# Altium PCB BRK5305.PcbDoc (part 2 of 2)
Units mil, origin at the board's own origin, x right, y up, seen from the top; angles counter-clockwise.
Board outline 4724.41 x 3149.61 mil, 4 copper layers (L1-Top, L2-Plane-1, L3-Plane-2, L4-Bottom), stack 60.6 mil thick; 66 components, 156 nets, 613 pads, 306 vias.
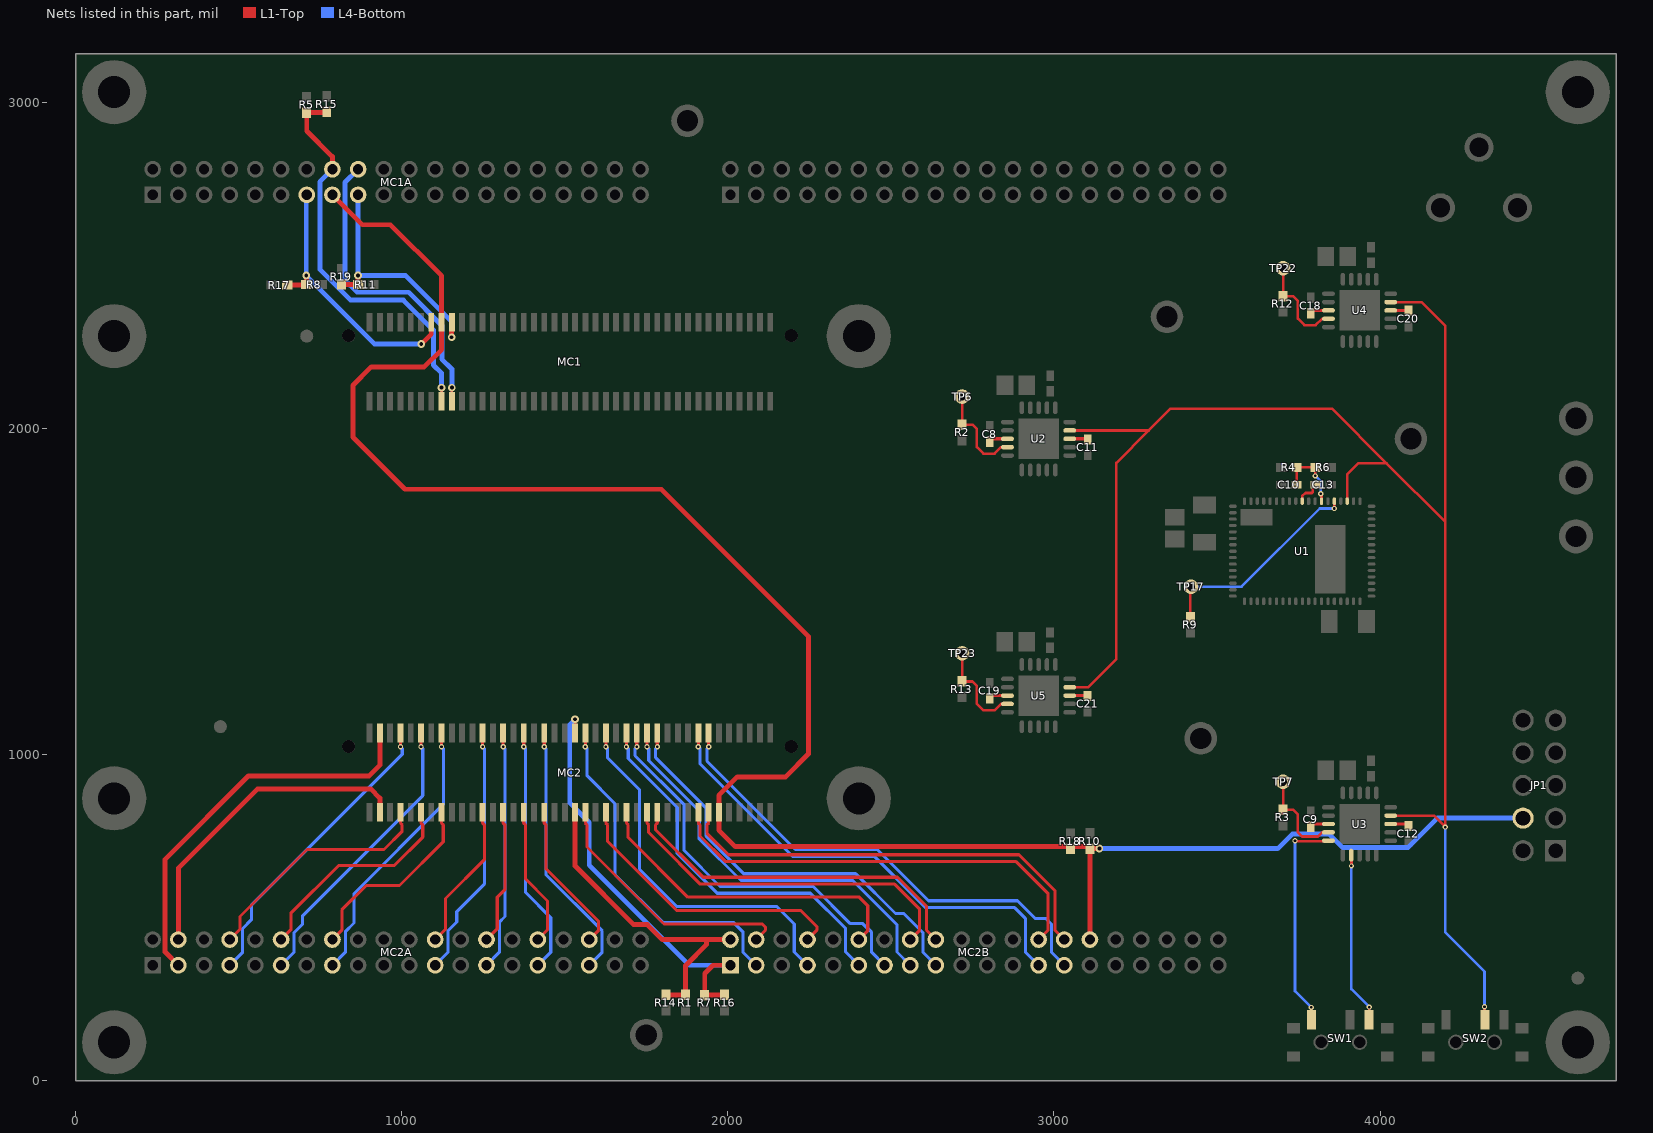
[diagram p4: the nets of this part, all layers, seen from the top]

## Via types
v1: diameter 16, hole 8, L1-Top to L4-Bottom, tented both sides, 140 vias
v2: diameter 23.62, hole 11.81, L1-Top to L4-Bottom, tented both sides, 74 vias
v3: diameter 15.99, hole 8, L1-Top to L4-Bottom, tented both sides, 52 vias
v4: diameter 30, hole 15, L1-Top to L4-Bottom, tented both sides, 40 vias

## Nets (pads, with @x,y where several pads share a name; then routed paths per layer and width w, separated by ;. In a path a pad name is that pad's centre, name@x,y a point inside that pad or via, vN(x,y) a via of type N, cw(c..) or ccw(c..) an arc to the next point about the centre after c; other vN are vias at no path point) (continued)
MC2-BN19: MC2.53 MC2B.13 | length 1221.2
  L1-Top w9.5: MC2.53@1720.47,1066.34 1720.47,1024.44 v1(1720.91,1024)
  L4-Bottom w9.5: v1(1720.91,1024) 1715.41,1018.5 1715.41,997 1865.71,846.7 1865.71,705.98 1975.7,596 2261.7,596 2375.7,482 2413.96,482 2440.96,455 2440.96,393.69 MC2B.13@2480.32,354.33
MC2-BN20: MC2.58 MC2B.18 | length 1097.6
  L1-Top w9.5: MC2.58@1783.46,823.43 1783.46,790.13 1778.22,784.88 1778.22,769.89 1924.11,624 2520,624 2608.93,535.07 2608.93,461.94 MC2B.18@2637.8,433.07
MC2-BN21: MC2.57 MC2B.17 | length 1286.4
  L1-Top w9.5: MC2.57@1783.46,1066.34 1783.47,1024.44 v1(1783.91,1024)
  L4-Bottom w9.5: v1(1783.91,1024) 1778.41,1018.5 1778.41,991 1933.35,836.05 1933.35,750.34 2048.7,635 2391.7,635 2513.85,512.85 2539.59,512.85 2598.44,454 2598.44,393.69 MC2B.17@2637.8,354.33
MC2-BN22: MC2.68 MC2B.28 | length 1368.2
  L1-Top w9.5: MC2.68@1940.95,823.43 1940.95,790.13 1935.7,784.88 1935.7,759.3 2002,693 2892.7,693 3003,582.7 3003,461.57 MC2B.28@3031.5,433.07
MC2-BN23: MC2.67 MC2B.27 | length 1494.7
  L1-Top w9.5: MC2.67@1940.95,1066.34 1940.95,1024.44 v1(1941.39,1024)
  L4-Bottom w9.5: v1(1941.39,1024) 1935.89,1018.5 1935.89,980.11 2055,861 2207,709 2458,709 2615,552 2887.84,552 2941.84,498 2975.14,498 2992.14,481 2992.14,393.69 MC2B.27@3031.5,354.33
MC2-BP0: MC2.8 MC2A.8 | length 749.8
  L1-Top w9.5: MC2A.8@472.44,433.07 504,464.63 504,503.7 709.3,709 945.31,709 1001.31,765 1001.31,784.88 996.06,790.13 MC2.8@996.06,823.43
MC2-BP1: MC2.7 MC2A.7 | length 933.5
  L1-Top w9.5: v1(996,1024) 996.06,1024.06 MC2.7@996.06,1066.34
  L4-Bottom w9.5: MC2A.7@472.44,354.33 512,393.89 512,467 538.76,493.76 538.76,538.32 1001.5,1001.06 1001.5,1018.5 v1(996,1024)
MC2-BP2: MC2.12 MC2A.12 | length 672.6
  L1-Top w9.5: MC2A.12@629.92,433.07 660,463.15 660,513.7 806.3,660 977.3,660 1064.3,747 1064.3,784.88 1059.06,790.13 MC2.12@1059.06,823.43
MC2-BP3: MC2.11 MC2A.11 | length 894.3
  L1-Top w9.5: v1(1058.99,1024) 1059.06,1024.06 MC2.11@1059.06,1066.34
  L4-Bottom w9.5: MC2A.11@629.92,354.33 669.48,393.89 669.48,454 696.24,480.76 696.24,505.94 1064.49,874.19 1064.49,1018.5 v1(1058.99,1024)
MC2-BP4: MC2.16 MC2A.16 | length 593.1
  L1-Top w9.5: MC2A.16@787.4,433.07 816.27,461.94 816.27,523.97 891.3,599 993.3,599 1127.3,732.99 1127.3,784.88 1122.05,790.13 MC2.16@1122.05,823.43
MC2-BP5: MC2.15 MC2A.15 | length 855.2
  L1-Top w9.5: v1(1121.98,1024) 1122.05,1024.06 MC2.15@1122.05,1066.34
  L4-Bottom w9.5: MC2A.15@787.4,354.33 826.96,393.89 826.96,457 853.72,483.76 853.72,573.72 1127.48,847.48 1127.48,1018.5 v1(1121.98,1024)
MC2-BP6: MC2.24 MC2A.24 | length 455
  L1-Top w9.5: MC2A.24@1102.36,433.07 1134,464.71 1134,559 1253.28,678.28 1253.28,784.88 1248.03,790.13 MC2.24@1248.03,823.43
MC2-BP7: MC2.23 MC2A.23 | length 776.9
  L1-Top w9.5: v1(1247.97,1024) 1248.03,1024.06 MC2.23@1248.03,1066.34
  L4-Bottom w9.5: MC2A.23@1102.36,354.33 1141.92,393.89 1141.92,460 1168.68,486.76 1168.68,518.38 1253.47,603.17 1253.47,1018.5 v1(1247.97,1024)
MC2-BP8: MC2.28 MC2A.28 | length 415.9
  L1-Top w9.5: MC2A.28@1259.84,433.07 1292.85,466.08 1292.85,562.85 1316.27,586.27 1316.27,784.88 1311.02,790.13 MC2.28@1311.02,823.43
MC2-BP9: MC2.27 MC2A.27 | length 737.8
  L1-Top w9.5: v1(1310.96,1024) 1311.02,1024.06 MC2.27@1311.02,1066.34
  L4-Bottom w9.5: MC2A.27@1259.84,354.33 1299.4,393.89 1299.4,486.5 1316.46,503.56 1316.46,1018.5 v1(1310.96,1024)
MC2-BP10: MC2.32 MC2A.32 | length 432.9
  L1-Top w9.5: MC2.32@1374.02,823.43 1374.02,790.13 1379.26,784.88 1379.26,619.04 1447,551.3 1447,462.75 MC2A.32@1417.32,433.07
MC2-BP11: MC2.31 MC2A.31 | length 762.8
  L1-Top w9.5: v1(1373.95,1024) 1374.02,1024.06 MC2.31@1374.02,1066.34
  L4-Bottom w9.5: v1(1373.95,1024) 1379.45,1018.5 1379.45,577.85 1456.88,500.42 1456.88,393.89 MC2A.31@1417.32,354.33
MC2-BP12: MC2.36 MC2A.36 | length 471.3
  L1-Top w9.5: MC2.36@1437.01,823.43 1437.01,790.13 1442.26,784.88 1442.26,650.05 1603.67,488.63 1603.67,461.94 MC2A.36@1574.8,433.07
MC2-BP13: MC2.35 MC2A.35 | length 801.9
  L1-Top w9.5: v1(1436.94,1024) 1437.01,1024.06 MC2.35@1437.01,1066.34
  L4-Bottom w9.5: v1(1436.94,1024) 1442.44,1018.5 1442.44,631.56 1614.36,459.64 1614.36,393.89 MC2A.35@1574.8,354.33
MC2-BP14: MC2.44 MC2B.4 | length 807.8
  L1-Top w9.5: MC2.44@1562.99,823.43 1562.99,790.13 1568.24,784.88 1568.24,716.76 1804,481 2105.49,481 2115.48,471 2115.48,461.94 MC2B.4@2086.61,433.07
MC2-BP15: MC2.43 MC2B.3 | length 1056.1
  L1-Top w9.5: v1(1562.93,1024) 1562.99,1024.06 MC2.43@1562.99,1066.34
  L4-Bottom w9.5: v1(1562.93,1024) 1568.43,1018.5 1568.43,934.87 1654,849.3 1654,632.3 1801.4,484.9 2018.4,484.9 2046,457.3 2046,394.95 MC2B.3@2086.61,354.33
MC2-BP16: MC2.48 MC2B.8 | length 893.5
  L1-Top w9.5: MC2.48@1625.98,823.43 1625.98,790.13 1631.23,784.88 1631.23,733.77 1843,522 2223.97,522 2272.97,473 2272.97,461.94 MC2B.8@2244.1,433.07
MC2-BP17: MC2.47 MC2B.7 | length 1147.6
  L1-Top w9.5: v1(1625.92,1024) 1625.98,1024.06 MC2.47@1625.98,1066.34
  L4-Bottom w9.5: v1(1625.92,1024) 1631.42,1018.5 1631.42,989.88 1729,892.3 1729,649 1844,534 2150.48,534 2203.48,481 2203.48,394.95 MC2B.7@2244.1,354.33
MC2-BP18: MC2.52 MC2B.12 | length 1016.2
  L1-Top w9.5: MC2.52@1688.98,823.43 1688.98,790.13 1694.22,784.88 1694.22,746.08 1877.3,563 2403,563 2429,537 2429,460.5 MC2B.12@2401.58,433.07
MC2-BP19: MC2.51 MC2B.11 | length 1174.8
  L1-Top w9.5: v1(1688.91,1024) 1688.98,1024.06 MC2.51@1688.98,1066.34
  L4-Bottom w9.5: v1(1688.91,1024) 1694.41,1018.5 1694.41,988.3 1844.71,838 1844.71,697.29 1967,575 2253,575 2360.96,467.04 2360.96,394.95 MC2B.11@2401.58,354.33
MC2-BP20: MC2.56 MC2B.16 | length 1097.6
  L1-Top w9.5: MC2.56@1751.97,823.43 1751.97,790.13 1757.22,784.88 1757.22,761.2 1785.52,732.89 1915.41,603 2511.3,603 2587.93,526.38 2587.93,461.94 MC2B.16@2559.06,433.07
MC2-BP21: MC2.55 MC2B.15 | length 1247.3
  L1-Top w9.5: v1(1751.91,1024) 1751.97,1024.06 MC2.55@1751.97,1066.34
  L4-Bottom w9.5: v1(1751.91,1024) 1757.41,1018.5 1757.41,982.3 1912.35,827.35 1912.35,741.65 2040,614 2383,614 2518.44,478.56 2518.44,394.95 MC2B.15@2559.06,354.33
MC2-BP22: MC2.66 MC2B.26 | length 1368.5
  L1-Top w9.5: MC2.66@1909.45,823.43 1909.45,790.13 1914.7,784.88 1914.7,750.6 1993.3,672 2884,672 2982,574 2982,462.32 MC2B.26@2952.76,433.07
MC2-BP23: MC2.65 MC2B.25 | length 1451.1
  L1-Top w9.5: v1(1909.39,1024) 1909.45,1024.06 MC2.65@1909.45,1066.34
  L4-Bottom w9.5: v1(1909.39,1024) 1914.89,1018.5 1914.89,971.42 2046.3,840 2198.3,688 2449.3,688 2606.3,531 2879.14,531 2912.14,498 2912.14,394.95 MC2B.25@2952.76,354.33
NetC8_1: C8.1 U2.3 | length 45
  L1-Top w10: C8.1@2812.28,1968.5 U2.3@2857.28,1968.5
NetC9_1: C9.1 U3.3 | length 45
  L1-Top w10: C9.1@3796.54,787.4 U3.3@3841.54,787.4
NetC10_1: C10.1 R4.1 R6.2 U1.56 | length 217.8
  L1-Top w8: R4.1@3743.82,1880.89 R6.2@3801.58,1880.89 v1@3801.58,1854.89 ; C10.1@3744.66,1828.47 R4.1@3744.66,1880.05 ; U1.56@3820.25,1777.43 v1@3820.25,1797.84
  L4-Bottom w8: v1(3801.2,1854.89) 3818.2,1837.89 v1(3818.2,1799.89)
NetC11_2: C11.2 U2.13 | length 53.2
  L1-Top w10: U2.13@3048.23,1968.5 C11.2@3101.42,1968.5
NetC12_2: C12.2 U3.13 | length 53.2
  L1-Top w10: U3.13@4032.48,787.4 C12.2@4085.67,787.4
NetC13_2: C13.2 U1.59 | length 74.8
  L1-Top w8: U1.59@3761.04,1777.01 3761.04,1792.47 3771.04,1802.47 3790.04,1802.47 3793.04,1805.47 C13.2@3793.04,1827.47
NetC18_1: C18.1 U4.3 | length 45
  L1-Top w10: C18.1@3796.54,2362.2 U4.3@3841.54,2362.2
NetC19_1: C19.1 U5.3 | length 45
  L1-Top w10: C19.1@2812.28,1181.1 U5.3@2857.28,1181.1
NetC20_2: C20.2 U4.13 | length 53.2
  L1-Top w10: U4.13@4032.48,2362.2 C20.2@4085.67,2362.2
NetC21_2: C21.2 U5.13 | length 53.2
  L1-Top w10: U5.13@3048.23,1181.1 C21.2@3101.42,1181.1
NetR2_1: R2.1 TP6.1 U2.4 | length 302.6
  L1-Top w8: TP6.1@2718.23,2098.07 R2.1@2718.23,2011.69 2749.61,2011.69 2763.23,1998.07 2763.23,1943.07 2783.23,1923.07 2818.23,1923.07 2838.07,1942.91 U2.4@2857.28,1942.91
NetR3_1: R3.1 TP7.1 U3.4 | length 296.8
  L1-Top w8: TP7.1@3702.48,916.97 3702.48,830.59 3733.86,830.59 3747.48,816.97 3747.48,761.97 3760.45,749 3809.51,749 3822.32,761.81 U3.4@3841.54,761.81
NetR9_1: R9.1 TP17.1 U1.54 | length 654.3
  L1-Top w8: R9.1@3418,1421.62 TP17.1@3418,1513 ; TP17.1@3418.62,1513.62 TP17.1@3420,1515 ; v1(3859.47,1754.89) U1.54@3859.46,1777.01
  L4-Bottom w8: TP17.1@3420,1515 3575,1515 3814.89,1754.89 v1(3859.47,1754.89)
NetR12_1: R12.1 TP22.1 U4.4 | length 302.6
  L1-Top w8: TP22.1@3702.48,2491.77 3702.48,2405.39 3733.86,2405.39 3747.48,2391.77 3747.48,2336.77 3767.48,2316.77 3802.48,2316.77 3822.32,2336.61 U4.4@3841.54,2336.61
NetR13_1: R13.1 TP23.1 U5.4 | length 302.6
  L1-Top w8: TP23.1@2718.23,1310.67 2718.23,1224.29 2749.61,1224.29 2763.23,1210.67 2763.23,1155.67 2783.23,1135.67 2818.23,1135.67 2838.07,1155.51 U5.4@2857.28,1155.51
NetSW1_1: SW1.1 U3.5 | length 674.4
  L1-Top w8: v1(3739,736) 3740.66,734.34 3841.54,734.34 U3.5@3841.54,736.22 ; SW1.1@3789,187.38 v1(3789,225)
  L4-Bottom w8: v1(3739,736) 3739,275 v1(3789,225)
NetSW1_3: SW1.3 U3.7 | length 526.8
  L1-Top w8: v1@3912.4,659.4 U3.7@3912.4,691.93 ; SW1.3@3967,187.47 v1(3967,226)
  L4-Bottom w8: v1(3912,659) 3912,281 v1(3967,226)
PWR_EN: SW2.2 U1.52 U2.14 U3.14 U4.14 U5.14 | length 5017
  L1-Top w8: U5.14@3048.23,1206.69 3103.69,1206.69 3191,1294 3191,1895 3290.09,1994.09 ; U2.14@3048.23,1994.09 3290.09,1994.09 ; U1.52@3898.99,1777.43 3898.99,1859.22 3932.77,1893 4020,1893 ; U3.14@4032.48,812.99 4165.01,812.99 v1(4200,778) 4200,1713 ; U4.14@4032.48,2387.8 4127.2,2387.8 4200,2315 4200,1713 ; SW2.2@4320,187.87 v1(4320,227) ; 3290.09,1994.09 3357,2061 3852,2061 4020,1893 ; 4020,1893 4200,1713
  L4-Bottom w8: v1(4200,778) 4200,455 4320,335 v1(4320,227)
VCCIO2: MC2.42 MC2B.2 R1.1 R14.2 | length 991.1
  L1-Top w15: MC2.42@1531.5,823.43 1531.5,658.5 1711,479 1753,479 1798.93,433.07 1935,433.07 ; R14.2@1810,263.62 R1.1@1870,263.62 1870,353.07 1935,418.07 1935,433.07 ; MC2B.2@2007.87,433.07 1935,433.07
VCCIO4: MC1.16 MC1A.16 R5.1 R15.2 | length 1245.7
  L1-Top w8: MC1.16@1122.05,2083.27 v2(1122.05,2125.54)
  L1-Top w15: R15.2@770,2971.38 767.13,2968.5 R5.1@708.66,2968.5 708.66,2912.34 787.4,2833.6 MC1A.16@787.4,2795.28
  L4-Bottom w15: MC1A.16@787.4,2795.28 749,2756.87 749,2488 843,2394 1005,2394 1097,2302 1097,2195 1122.05,2169.95 v2(1122.05,2125.54)
VCCIO5: MC2.41 MC2B.1 R7.1 R16.2 | length 1298.7
  L1-Top w8: MC2.41@1531.5,1066.34 v2(1531.5,1108.61)
  L1-Top w9.5: v2(1531.5,1108.61) v2@1531.56,1108.68
  L1-Top w15: R16.2@1990,263.62 1989,262.62 R7.1@1929,262.62 1929,329 1954.33,354.33 MC2B.1@2007.87,354.33
  L4-Bottom w15: v2(1531.5,1108.61) 1515,1092.12 1515,852 1575,792 1575,661 1881.67,354.33 MC2B.1@2007.87,354.33
VCCPD2: MC1.13 MC1A.13 R8.1 R17.2 | length 852.5
  L1-Top w15: R17.2@648.62,2440 706.38,2440 R8.1@707.38,2441 v2@707.38,2468.62 ; v2(1060,2259) 1090.55,2289.55 MC1.13@1090.55,2326.18
  L4-Bottom w15: MC1A.13@707,2714.87 v2(707,2469) 917,2259 v2(1060,2259)
VCCPD4: JP1.4 MC1.15 MC1A.15 MC2.70 MC2B.30 R10.1 R18.2 | length 6424.4
  L1-Top w15: MC1A.15@787.4,2716.54 878.94,2625 965,2625 1122.05,2467.95 MC1.15@1122.05,2326.18 1122.05,2242.05 1069,2189 907,2189 850,2132 850,1974 1010,1814 1796,1814 2247,1363 2247,1002 2177,932 2029,932 1972.44,875.44 MC2.70@1972.44,823.43 1972.44,768.56 2023,718 3103.38,718 R10.1@3110,711.38 3110,433.31 MC2B.30@3110.24,433.07 ; R10.1@3110.62,712 v2(3139,712)
  L4-Bottom w15: v2(3139,712) 3686.01,712 3730.51,756.5 3844.5,756.5 3886,715 4085,715 4175.51,805.51 JP1.4@4438.19,805.51
VCCPD5: MC1.17 MC1A.17 R11.1 R19.2 | length 765.6
  L1-Top w15: R19.2@815,2441.38 866,2441.38 R11.1@866.38,2441 v2@866.38,2468.62 ; v2(1153,2280) MC1.17@1153,2325.64
  L4-Bottom w15: MC1A.17@866,2716.39 v2(866,2469) 1012,2469 1153,2328 v2(1153,2280)
VREF2: MC2.4 MC2A.4 | length 992.8
  L1-Top w15: MC2A.4@314.96,433.07 314.96,651.96 558,895 905,895 933.07,866.93 MC2.4@933.07,823.43
VREF4: MC1.18 MC1A.18 | length 956.9
  L1-Top w8: MC1.18@1153.54,2083.27 v2(1153.54,2125.54)
  L4-Bottom w15: MC1A.18@866.14,2795.28 826,2755.13 826,2455 863,2418 1021,2418 1123,2316 1123,2213 1153.54,2182.46 v2(1153.54,2125.54)
VREF5: MC2.3 MC2A.3 | length 1218.5
  L1-Top w15: MC2A.3@314.96,354.33 274.31,394.98 274.31,679.31 530,935 900,935 933.07,968.07 MC2.3@933.07,1066.34
pads on no net: JP1.6 JP1.7 JP1.8 MC1.14 MC1.81 MC1.82 MC1A.14 MC2.81 MC2.82 P1.3 SW1.0 SW2.0 U1.14 U1.15 U1.16 U1.17 U1.18 U1.19 U1.20 U1.21 U1.22 U1.23 U1.24 U1.25 U1.26 U1.44 U1.45 U1.46 U1.47 U1.48 U1.49 U1.50 U1.51 U1.57 U1.58 U1.60 U1.61 U1.62 U1.63 U2.5 U2.10 U2.11 U3.6 U3.9 U3.11 U4.5 U4.6 U4.7 U4.10 U5.5 U5.6 U5.7

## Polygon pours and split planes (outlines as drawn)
+1.35VDD on L1-Top "U3-1.35" (solid, pour order 23): 3862.48,806.97 3767.48,806.97 3767.48,996.97 3862.48,996.97 3862.48,906.97 3922.48,906.97 3922.48,861.97 3862.48,861.97
+VDC on L1-Top "U3-VDC" (solid, pour order 29): 4057.48,826.97 4012.48,826.97 4012.48,861.97 3952.48,861.97 3952.48,951.97 4057.48,951.97
DGND on L1-Top "U3-DGND-Therm" (solid, pour order 33): 3872.48,996.97 3872.48,856.97 3867.48,856.97 3867.48,721.97 3677.48,721.97 3677.48,651.97 4107.48,651.97 4107.48,756.97 4062.48,756.97 4062.48,771.97 4007.48,771.97 4007.48,856.51 3952.48,856.51 3952.48,961.97 3997.48,961.97 3997.48,996.97
+3.3VDD on L1-Top "U5-3.3" (solid, pour order 24): 2878.23,1200.67 2783.23,1200.67 2783.23,1390.67 2878.23,1390.67 2878.23,1300.67 2938.23,1300.67 2938.23,1255.67 2878.23,1255.67
+VDC on L1-Top "U5-VDC" (solid, pour order 30): 3073.23,1220.67 3028.23,1220.67 3028.23,1255.67 2968.23,1255.67 2968.23,1345.67 3073.23,1345.67
DGND on L1-Top "U5-DGND-Therm" (solid, pour order 34): 2888.23,1390.67 2888.23,1250.67 2883.23,1250.67 2883.23,1115.67 2693.23,1115.67 2693.23,1045.67 3123.23,1045.67 3123.23,1150.67 3078.23,1150.67 3078.23,1165.67 3023.23,1165.67 3023.23,1250.21 2968.23,1250.21 2968.23,1355.67 3013.23,1355.67 3013.23,1390.67
+1.2VDD on L1-Top "U2-1.2" (solid, pour order 28): 2878.23,1988.07 2783.23,1988.07 2783.23,2178.07 2878.23,2178.07 2878.23,2088.07 2938.23,2088.07 2938.23,2043.07 2878.23,2043.07
+1.1VDD on L1-Top "+1.1V_U1" (solid, remove dead copper, pour order 37): 3561.04,1688.29 3561.04,1518.47 3521.04,1518.47 3501.04,1568.47 3456.04,1588.47 3323.2,1588.47 3323.2,1688.29
DGND on L1-Top "DGND_Poly" (solid, remove dead copper, pour order 42): 3185,964.46 3595.14,554.33 4195,554.33 4195,2675 3595.13,2675 3295.18,2375.04 2850.04,2375.04 2610,2135 2610,1163.93 2809.46,964.46
DGND on L1-Top "+DGND_U1" (solid, remove dead copper, pour order 39): 3926.04,1363.47 3926.04,1508.47 3891.04,1533.47 3831.04,1533.47 3791.04,1498.47 3791.04,1393.47 3821.04,1363.47
+VDC on L1-Top "+VDC_U1" (solid, remove dead copper, pour order 38): 3931.04,1338.47 3931.04,1648.47 3991.04,1648.47 4026.04,1613.47 4026.04,1338.47
DGND on L1-Top "+DGND_U1_2" (solid, remove dead copper, pour order 40): 3671.04,1697.47 3323.2,1697.47 3323.2,1803.47 3671.04,1803.47
+VDC on L1-Top "U2-VDC" (solid, pour order 32): 3073.23,2008.07 3028.23,2008.07 3028.23,2043.07 2968.23,2043.07 2968.23,2133.07 3073.23,2133.07
DGND on L1-Top "U2-DGND-Therm" (solid, pour order 36): 2888.23,2178.07 2888.23,2038.07 2883.23,2038.07 2883.23,1903.07 2693.23,1903.07 2693.23,1833.07 3123.23,1833.07 3123.23,1938.07 3078.23,1938.07 3078.23,1953.07 3023.23,1953.07 3023.23,2037.62 2968.23,2037.62 2968.23,2143.07 3013.23,2143.07 3013.23,2178.07
DGND on L1-Top "U4-DGND-Therm" (solid, pour order 35): 3872.48,2571.77 3872.48,2431.77 3867.48,2431.77 3867.48,2296.77 3677.48,2296.77 3677.48,2226.77 4107.48,2226.77 4107.48,2331.77 4062.48,2331.77 4062.48,2346.77 4007.48,2346.77 4007.48,2431.32 3952.48,2431.32 3952.48,2536.77 3997.48,2536.77 3997.48,2571.77
+VDC on L1-Top "U4-VDC" (solid, pour order 31): 4057.48,2401.77 4012.48,2401.77 4012.48,2436.77 3952.48,2436.77 3952.48,2526.77 4057.48,2526.77
+2.5VDD on L1-Top "U4-2.5" (solid, pour order 27): 3862.48,2381.77 3767.48,2381.77 3767.48,2571.77 3862.48,2571.77 3862.48,2481.77 3922.48,2481.77 3922.48,2436.77 3862.48,2436.77
+VDC on L4-Bottom "+VDC" (solid, pour order 22): 4675,1950 4150,1950 4150,2525 3975,2525 3975,2449.8 3999.95,2424.86 3999.95,2136 3875,1991 3875,1775 3925,1725 3925,925 4025,825 4150,825 4150,1750 4675,1750
+VDC on L4-Bottom "+VDC" (solid, pour order 26): 2975,1350 2975,1275 3050,1200 3950,1200 3950,1350
+VDC on L4-Bottom "+VDC" (solid, pour order 25): 2975,2137.4 2975,2062.4 3050,1987.4 4050,1987.4 4050,2137.4
DGND on L2-Plane-1 (split plane): 4704.31,20.1 20.1,20.1 20.1,3129.51 4704.31,3129.51
DGND on L3-Plane-2 (split plane): 3539.91,2674.18 3235.82,2370.09 2860,2370.09 2857.39,2369.74 2856.38,2369.33 2854.96,2368.73 2852.87,2367.13 2470.82,1985.09 1204.18,1985.09 1107.13,2082.13 1105.04,2083.73 1102.61,2084.74 1100,2085.09 925,2085.09 922.39,2084.74 919.96,2083.73 917.87,2082.13 916.27,2080.04 915.26,2077.61 914.91,2075 914.91,1746.35 528.09,2133.18 528.09,2739.91 675,2739.91 677.61,2740.26 680.04,2741.27 682.13,2742.87 683.73,2744.96 684.74,2747.39 685.09,2750 685.09,2864.91 3539.91,2864.91
+2.5VDD on L3-Plane-2 (split plane): 507.91,2129 508.26,2126.39 509.27,2123.96 510.87,2121.87 907.87,1724.87 909.96,1723.27 912.39,1722.26 915,1721.91 2935,1721.91 2937.61,1722.26 2940.04,1723.27 2942.13,1724.87 3658.13,2440.87 3659.74,2442.96 3660.74,2445.39 3661.09,2448 3661.09,2601.91 3839.91,2601.91 3839.91,2429.18 3267.87,1857.13 3266.27,1855.04 3265.26,1852.61 3264.91,1850 3264.91,1560.09 848.18,1560.09 438.09,1970.18 438.09,2739.91 507.91,2739.91
+1.1VDD on L3-Plane-2 (split plane): 4114.91,2004.18 3670.82,1560.09 3285.09,1560.09 3285.09,1845.82 3857.13,2417.87 3858.74,2419.96 3859.74,2422.39 3860.09,2425 3860.09,2606.11 3860.74,2606.96 3861.74,2609.39 3862.09,2612 3861.74,2614.61 3860.74,2617.04 3859.13,2619.13 3858,2620 3857.13,2621.13 3855.04,2622.73 3852.61,2623.74 3850,2624.09 3847.39,2623.74 3844.96,2622.73 3844.11,2622.09 3651,2622.09 3648.39,2621.74 3645.96,2620.73 3643.87,2619.13 3642.27,2617.04 3641.26,2614.61 3640.91,2612 3640.91,2452.18 2930.82,1742.09 935.09,1742.09 935.09,2064.91 1095.82,2064.91 1192.87,1967.87 1194.96,1966.27 1197.39,1965.26 1200,1964.91 2475,1964.91 2477.61,1965.26 2480.04,1966.27 2482.13,1967.87 2864.18,2349.91 3240,2349.91 3242.61,2350.26 3245.04,2351.27 3247.13,2352.87 3557.13,2662.87 3558.74,2664.96 3559.74,2667.39 3560.09,2670 3560.09,2875 3559.74,2877.61 3558.74,2880.04 3557.13,2882.13 3555.04,2883.73 3552.61,2884.74 3550,2885.09 675,2885.09 672.39,2884.74 669.96,2883.73 667.87,2882.13 666.27,2880.04 665.26,2877.61 664.91,2875 664.91,2760.09 360.09,2760.09 360.09,3129.51 4114.91,3129.51
DGND on L3-Plane-2 (split plane): 4704.31,20.1 20.1,20.1 20.1,3129.51 339.91,3129.51 339.91,2750 340.26,2747.39 341.27,2744.96 342.87,2742.87 344.96,2741.27 347.39,2740.26 350,2739.91 417.91,2739.91 417.91,1966 418.26,1963.39 419.27,1960.96 420.87,1958.87 836.87,1542.87 838.96,1541.27 840.38,1540.67 841.39,1540.26 844,1539.91 3675,1539.91 3677.61,1540.26 3680.04,1541.27 3682.13,1542.87 4132.13,1992.87 4133.74,1994.96 4134.74,1997.39 4135.09,2000 4135.09,3129.51 4704.31,3129.51

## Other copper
L1-Top:
  pour cut-out: 3564,1481 3564,1700 3674,1700 3674,1816 3959,1816 3959,1656 3959,1489 3892,1489 3892,1706 3799,1706 3799,1491.04 3788.96,1481
L4-Bottom:
  rectangle net +1.35VDD: 3750,875 3825,1000
  rectangle net +1.2VDD: 2765,2057.44 2840,2182.44
  rectangle net +3.3VDD: 2770,1310 2825,1410
L3-Plane-2 (plane layer: these items are gaps in the copper):
  lines w20: 350,3149.61 350,2750 675,2750 675,2875 3550,2875 3550,2670 3240,2360 2860,2360 2475,1975 1200,1975 1100,2075 925,2075 925,1732 ; 428,2750 428,1966 844,1550 3275,1550 ; 518,2750 518,2129 915,1732 2935,1732 3651,2448 3651,2612 3852,2612 ; 3850,2614 3850,2425 3275,1850 3275,1550 ; 4125,3149.61 4125,2000 3675,1550 3575,1550 3275,1550

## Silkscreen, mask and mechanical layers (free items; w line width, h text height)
Top Overlay:
  lines w7.99: 0,748.03 2519.69,748.03 2519.69,2401.58 0,2401.58
  lines w10: 780,2345 780,2380 810,2410 ; 2650,1050 2650,1230 2680,1260 ; 2650,1837.4 2650,2017.4 2680,2047.4 ; 3634.25,656.3 3634.25,836.3 3664.25,866.3 ; 3634.25,2231.1 3634.25,2411.1 3664.25,2441.1
  text "VCCIO4" at 830,2855 h30 r90
  text "GND" at 255.91,2854.33 h30 r90
  text "MC1-ASP0" at 334.65,2854.33 h30 r90
  text "+1.1VDD" at 413.39,2854.33 h30 r90
  text "+1.1VDD" at 492.13,2854.33 h30 r90
  text "+1.1VDD" at 570.87,2854.33 h30 r90
  text "+1.1VDD" at 649.61,2854.33 h30 r90
  text "NC" at 728.35,2854.33 h30 r90
  text "VREF4" at 885.83,2854.33 h30 r90
  text "GND" at 964.57,2854.33 h30 r90
  text "MC1-A0" at 1043.31,2854.33 h30 r90
  text "MC1-Bp0" at 1122.05,2854.33 h30 r90
  text "MC1-Bn0" at 1200.79,2854.33 h30 r90
  text "MC1-Bp2" at 1279.53,2854.33 h30 r90
  text "MC1-Bn2" at 1358.27,2854.33 h30 r90
  text "MC1-Bp4" at 1437.01,2854.33 h30 r90
  text "MC1-Bn4" at 1515.75,2854.33 h30 r90
  text "MC1-Bp6" at 1594.49,2854.33 h30 r90
  text "MC1-Bn6" at 1673.23,2854.33 h30 r90
  text "GND" at 1751.97,2854.33 h30 r90
  text "MC1-A2" at 2027.56,2854.33 h30 r90
  text "MC1-Bp8" at 2106.3,2854.33 h30 r90
  text "MC1-Bn8" at 2185.04,2854.33 h30 r90
  text "MC1-Bp10" at 2263.78,2854.33 h30 r90
  text "MC1-Bn10" at 2342.52,2854.33 h30 r90
  text "MC1-Bp12" at 2421.26,2854.33 h30 r90
  text "MC1-Bn12" at 2500,2854.33 h30 r90
  text "MC1-Bp14" at 2578.74,2854.33 h30 r90
  text "MC1-Bn14" at 2657.48,2854.33 h30 r90
  text "GND" at 2736.22,2854.33 h30 r90
  text "MC1-A4" at 2814.96,2854.33 h30 r90
  text "MC1-Bp16" at 2893.7,2854.33 h30 r90
  text "MC1-Bn16" at 2972.44,2854.33 h30 r90
  text "MC1-A6" at 3051.18,2854.33 h30 r90
  text "MC1-A7" at 3129.92,2854.33 h30 r90
  text "MC1-ASP2" at 3208.66,2854.33 h30 r90
  text "MC1-ASP4" at 3287.4,2854.33 h30 r90
  text "MC1-ASP6" at 3366.14,2854.33 h30 r90
  text "MC1-ASP7" at 3444.88,2854.33 h30 r90
  text "GND" at 3523.62,2854.33 h30 r90
  text "+5VDC" at 3945,2715 h40
  text "GND" at 255.91,2580.9 h30 r90
  text "GND" at 964.57,2580.9 h30 r90
  text "GND" at 1751.97,2580.9 h30 r90
  text "GND" at 2736.22,2577.29 h30 r90
  text "GND" at 3523.62,2577.29 h30 r90
  text "MC1-A1" at 1043.31,2505.92 h30 r90
  text "MC1-A3" at 2027.56,2492.32 h30 r90
  text "MC1-A5" at 2814.96,2492.32 h30 r90
  text "+5VUSB" at 334.65,2490.93 h30 r90
  text "VCCPD2" at 728.35,2490.93 h30 r90
  text "VCCPD4" at 807.09,2490.93 h30 r90
  text "VCCPD5" at 885.83,2490.93 h30 r90
  text "MC1-Bp1" at 1122.05,2475.93 h30 r90
  text "MC1-Bn1" at 1200.79,2475.93 h30 r90
  text "+1.2VDD" at 649.61,2470.94 h30 r90
  text "CLKOUT1" at 3129.92,2467.33 h30 r90
  text "+3.3VDD" at 413.39,2465.94 h30 r90
  text "+2.5VDD" at 492.13,2465.94 h30 r90
  text "MC1-Bp3" at 1279.53,2465.94 h30 r90
  text "MC1-Bn3" at 1358.27,2465.94 h30 r90
  text "MC1-Bp5" at 1437.01,2465.94 h30 r90
  text "MC1-Bn5" at 1515.75,2465.94 h30 r90
  text "MC1-Bp7" at 1594.49,2465.94 h30 r90
  text "MC1-Bn7" at 1673.23,2465.94 h30 r90
  text "MC1-Bp9" at 2106.3,2462.33 h30 r90
  text "MC1-Bn9" at 2185.04,2462.33 h30 r90
  text "CLKOUT0" at 3051.18,2457.33 h30 r90
  text "CLKOUT2" at 3208.66,2457.33 h30 r90
  text "MC1-Bp11" at 2263.78,2447.33 h30 r90
  text "MC1-Bn11" at 2342.52,2447.33 h30 r90
  text "MC1-ASP1" at 3287.4,2442.33 h30 r90
  text "+1.35VDD" at 570.87,2440.95 h30 r90
  text "MC1-Bp13" at 2421.26,2437.34 h30 r90
  text "MC1-Bn13" at 2500,2437.34 h30 r90
  text "MC1-Bp15" at 2578.74,2437.34 h30 r90
  text "MC1-Bn15" at 2657.48,2437.34 h30 r90
  text "MC1-Bp17" at 2893.7,2437.34 h30 r90
  text "MC1-Bn17" at 2972.44,2437.34 h30 r90
  text "MC1-ASP3" at 3366.14,2432.34 h30 r90
  text "MC1-ASP5" at 3444.88,2432.34 h30 r90
  text "+5VDC<->+5VUSB" at 4160,2105 h40 r270
  text "POWER SELECT" at 4215,2070 h40 r270
  text "BRK5305 - 20151116" at 1181.1,1476.38 h40
  text "JTAG" at 4135,1145 h40
  text "GND" at 255.91,492.13 h30 r90
  text "VREF2" at 334.65,492.13 h30 r90
  text "MC2-A0" at 413.39,492.13 h30 r90
  text "MC2-Bp0" at 492.13,492.13 h30 r90
  text "MC2-Bn0" at 570.87,492.13 h30 r90
  text "MC2-Bp2" at 649.61,492.13 h30 r90
  text "MC2-Bn2" at 728.35,492.13 h30 r90
  text "MC2-Bp4" at 807.09,492.13 h30 r90
  text "MC2-Bn4" at 885.83,492.13 h30 r90
  text "GND" at 964.57,492.13 h30 r90
  text "MC2-A2" at 1043.31,492.13 h30 r90
  text "MC2-Bp6" at 1122.05,492.13 h30 r90
  text "MC2-Bn6" at 1200.79,492.13 h30 r90
  text "MC2-Bp8" at 1279.53,492.13 h30 r90
  text "MC2-Bn8" at 1358.27,492.13 h30 r90
  text "MC2-Bp10" at 1437.01,492.13 h30 r90
  text "MC2-Bn10" at 1515.75,492.13 h30 r90
  text "MC2-Bp12" at 1594.49,492.13 h30 r90
  text "MC2-Bn12" at 1673.23,492.13 h30 r90
  text "GND" at 1751.97,492.13 h30 r90
  text "VCCIO2" at 2027.56,492.13 h30 r90
  text "MC2-Bp14" at 2106.3,492.13 h30 r90
  text "MC2-Bn14" at 2185.04,492.13 h30 r90
  text "MC2-Bp16" at 2263.78,492.13 h30 r90
  text "MC2-Bn16" at 2342.52,492.13 h30 r90
  text "MC2-Bp18" at 2421.26,492.13 h30 r90
  text "MC2-Bn18" at 2500,492.13 h30 r90
  text "MC2-Bp20" at 2578.74,492.13 h30 r90
  text "MC2-Bn20" at 2657.48,492.13 h30 r90
  text "GND" at 2736.22,492.13 h30 r90
  text "MC2-A4" at 2814.96,492.13 h30 r90
  text "MC2-A6" at 2893.7,492.13 h30 r90
  text "MC2-Bp22" at 2972.44,492.13 h30 r90
  text "MC2-Bn22" at 3051.18,492.13 h30 r90
  text "VCCPD4" at 3129.92,492.13 h30 r90
  text "JTAG TCK" at 3208.66,492.13 h30 r90
  text "JTAG TDI" at 3287.4,492.13 h30 r90
  text "JTAG TMS" at 3366.14,492.13 h30 r90
  text "JTAG TDO" at 3444.88,492.13 h30 r90
  text "GND" at 3523.62,492.13 h30 r90
  text "DRAM IO" at 3775,380 h40
  text "BRK Power" at 4120,380 h40
  text "Enable" at 4180,325 h40
  text "Voltage" at 3775,320 h40
  text "ON<->OFF" at 4140,255 h40
  text "1.35<->1.5" at 3725,250 h40
  text "GND" at 255.91,219.16 h30 r90
  text "GND" at 964.57,219.16 h30 r90
  text "GND" at 1751.97,219.16 h30 r90
  text "GND" at 3523.62,218.7 h30 r90
  text "GND" at 2736.22,215.09 h30 r90
  text "VREF5" at 334.65,159.18 h30 r90
  text "MC2-A1" at 413.39,139.18 h30 r90
  text "VCCIO5" at 2055,130 h30 r90
  text "CLKINp" at 3366.14,130.11 h30 r90
  text "CLKINn" at 3444.88,130.11 h30 r90
  text "MC2-A3" at 1043.31,129.19 h30 r90
  text "MC2-A5" at 2814.96,125.11 h30 r90
  text "MC2-A7" at 2893.7,125.11 h30 r90
  text "MC2-Bp1" at 492.13,109.19 h30 r90
  text "MC2-Bn1" at 570.87,109.19 h30 r90
  text "MC2-Bp3" at 649.61,99.2 h30 r90
  text "MC2-Bn3" at 728.35,99.2 h30 r90
  text "MC2-Bp5" at 807.09,99.2 h30 r90
  text "MC2-Bn5" at 885.83,99.2 h30 r90
  text "MC2-Bp7" at 1122.05,99.2 h30 r90
  text "MC2-Bn7" at 1200.79,99.2 h30 r90
  text "MC2-Bp9" at 1279.53,99.2 h30 r90
  text "MC2-Bn9" at 1358.27,99.2 h30 r90
  text "MC2-Bp11" at 1437.01,84.2 h30 r90
  text "MC2-Bn11" at 1515.75,84.2 h30 r90
  text "MC2-Bp21" at 2578.74,75.13 h30 r90
  text "MC2-Bn21" at 2657.48,75.13 h30 r90
  text "MC2-ASP1" at 3287.4,75.13 h30 r90
  text "MC2-Bp13" at 1594.49,74.2 h30 r90
  text "MC2-Bn13" at 1673.23,74.21 h30 r90
  text "MC2-Bp15" at 2106.3,70.13 h30 r90
  text "MC2-Bn15" at 2185.04,70.13 h30 r90
  text "MC2-Bp17" at 2263.78,70.13 h30 r90
  text "MC2-Bn17" at 2342.52,70.13 h30 r90
  text "MC2-Bp19" at 2421.26,70.13 h30 r90
  text "MC2-Bn19" at 2500,70.13 h30 r90
  text "+3.3Vaux" at 3129.92,70.13 h30 r90
  text "MC2-Bp23" at 2972.44,65.13 h30 r90
  text "MC2-Bn23" at 3051.18,65.13 h30 r90
  text "MC2-ASP0" at 3208.66,65.13 h30 r90
Outline:
  the board outline again, w8
Fab Notes:
  drawing of 295 lines, arcs and shapes, not listed
  text "NOTES" at -208.59,5847.53 h50
  text "1. MATERIAL SELECTION:" at -208.59,5747.53 h50
  text "4-LAYER, 370HR, 0.062\" +/- 0.005 THICK" at -83.59,5672.53 h50
  text "SURFACE FINISH: ENIG (ELECTROLESS NICKEL, IMMERSION GOLD)" at -83.59,5597.53 h50
  text "2. SOLDER RESIST: GREEN LPI" at -208.59,5472.53 h50
  text "3. SILKSCREEN: WHITE / DO NOT REMOVE OVER TENTED VIAS." at -208.59,5347.53 h50
  text "4. LOT CODE IDENTIFICATION: ADD TO SILKSCREEN" at -208.59,5222.53 h50
  text "5. DRILL SIZES ARE FINISHED SIZE AFTER PLATING." at -208.59,5097.53 h50
  text "6. ELECTRICAL BARE BOARD TEST REQUIRED" at -208.59,4972.53 h50
  text "7. FABRICATE TO MEET EU ROHS DIRECTIVE" at -208.59,4847.53 h50
  text "8. PANELIZATION:" at -208.59,4727.09 h50
  text "2-PIECES PER PANEL" at -83.59,4652.09 h50
  text "0.25-IN RAILS ON ALL SIDES" at -83.59,4577.09 h50
  text "0.25-IN TAB ROUTING WITH MOUSE-BITES FOR BOARD SEPARATION" at -83.59,4502.09 h50
  text "MOUSE BITE LOCATIONS INDICATED BY :::" at -80.37,4418.35 h50
  text ":::" at 2322.83,3208.66 h50 r180
  text "Layer" at 5317.07,2903 h50
  text "Name" at 5662,2903 h50
  text "Material" at 6440.12,2903 h50
  text "Thickness" at 7159.93,2903 h50
  text "Constant" at 7704.79,2903 h50
  text "Board Layer Stack" at 8183.01,2903 h50
  text "1" at 5317.07,2803 h50
  text "Top Overlay" at 5662,2803 h50
  text "2" at 5317.07,2703 h50
  text "Top Solder" at 5662,2703 h50
  text "Solder Resist" at 6440.12,2703 h50
  text "0.40mil" at 7159.93,2703 h50
  text "3.5" at 7704.79,2703 h50
  text "3" at 5317.07,2603 h50
  text "L1-Top" at 5662,2603 h50
  text "Copper" at 6440.12,2603 h50
  text "2.10mil" at 7159.93,2603 h50
  text "4" at 5317.07,2503 h50
  text "Dielectric1" at 5662,2503 h50
  text "370HR" at 6440.12,2503 h50
  text "7.30mil" at 7159.93,2503 h50
  text "4.2" at 7704.79,2503 h50
  text "5" at 5317.07,2403 h50
  text "L2-Plane-1" at 5662,2403 h50
  text "Copper" at 6440.12,2403 h50
  text "1.40mil" at 7159.93,2403 h50
  text "6" at 5317.07,2303 h50
  text "Dielectric 3" at 5662,2303 h50
  text "370HR" at 6440.12,2303 h50
  text "39.00mil" at 7159.93,2303 h50
  text "4.2" at 7704.79,2303 h50
  text "7" at 5317.07,2203 h50
  text "L3-Plane-2" at 5662,2203 h50
  text "Copper" at 6440.12,2203 h50
  text "1.40mil" at 7159.93,2203 h50
  text "8" at 5317.07,2103 h50
  text "Dielectric 2" at 5662,2103 h50
  text "370HR" at 6440.12,2103 h50
  text "7.30mil" at 7159.93,2103 h50
  text "4.2" at 7704.79,2103 h50
  text "9" at 5317.07,2003 h50
  text "L4-Bottom" at 5662,2003 h50
  text "Copper" at 6440.12,2003 h50
  text "2.10mil" at 7159.93,2003 h50
  text "10" at 5317.07,1903 h50
  text "Bottom Solder" at 5662,1903 h50
  text "Solder Resist" at 6440.12,1903 h50
  text "0.40mil" at 7159.93,1903 h50
  text "3.5" at 7704.79,1903 h50
  text "11" at 5317.07,1803 h50
  text "Bottom Overlay" at 5662,1803 h50
  text ":::" at -19.69,1535.43 h50 r90
  text ":::" at 4783.46,1377.95 h50 r270
  text ":::" at 2283.46,-59.06 h50
Drill Drawing:
  drawing of 409 lines, arcs and shapes, not listed
  text "Symbol" at 3459.67,5639.76 h60
  text "Count" at 3886.56,5639.76 h60
  text "Hole Size" at 4389.76,5639.76 h60
  text "Plated" at 5309.5,5639.76 h60
  text "Hole Type" at 5736.39,5639.76 h60
  text "Drill Layer Pair" at 6353.23,5639.76 h60
  text "Via/Pad" at 7349.94,5639.76 h60
  text "Pad Shape" at 7846.81,5639.76 h60
  text "Technology" at 8473.65,5639.76 h60
  text "1" at 3886.56,5514.76 h50
  text "40.00mil (1.016mm)" at 4389.76,5514.76 h50
  text "PTH" at 5309.5,5514.76 h50
  text "Round" at 5736.39,5514.76 h50
  text "L1-Top - L4-Bottom" at 6353.23,5514.76 h50
  text "Pad" at 7349.94,5514.76 h50
  text "Rounded" at 7846.81,5514.76 h50
  text "Drilled" at 8473.65,5514.76 h50
  text "3" at 3886.56,5389.76 h50
  text "59.06mil (1.500mm)" at 4389.76,5389.76 h50
  text "PTH" at 5309.5,5389.76 h50
  text "Round" at 5736.39,5389.76 h50
  text "L1-Top - L4-Bottom" at 6353.23,5389.76 h50
  text "Pad" at 7349.94,5389.76 h50
  text "Rounded" at 7846.81,5389.76 h50
  text "Drilled" at 8473.65,5389.76 h50
  text "4" at 3886.56,5264.76 h50
  text "35.43mil (0.900mm)" at 4389.76,5264.76 h50
  text "PTH" at 5309.5,5264.76 h50
  text "Round" at 5736.39,5264.76 h50
  text "L1-Top - L4-Bottom" at 6353.23,5264.76 h50
  text "Pad" at 7349.94,5264.76 h50
  text "Rounded" at 7846.81,5264.76 h50
  text "Drilled" at 8473.65,5264.76 h50
  text "4" at 3886.56,5139.76 h50
  text "40.16mil (1.020mm)" at 4389.76,5139.76 h50
  text "PTH" at 5309.5,5139.76 h50
  text "Round" at 5736.39,5139.76 h50
  text "L1-Top - L4-Bottom" at 6353.23,5139.76 h50
  text "Pad" at 7349.94,5139.76 h50
  text "Rounded" at 7846.81,5139.76 h50
  text "Drilled" at 8473.65,5139.76 h50
  text "5" at 3886.56,5014.76 h50
  text "25.00mil (0.635mm)" at 4389.76,5014.76 h50
  text "PTH" at 5309.5,5014.76 h50
  text "Round" at 5736.39,5014.76 h50
  text "L1-Top - L4-Bottom" at 6353.23,5014.76 h50
  text "Pad" at 7349.94,5014.76 h50
  text "Rounded" at 7846.81,5014.76 h50
  text "Drilled" at 8473.65,5014.76 h50
  text "8" at 3886.56,4889.76 h50
  text "65.00mil (1.651mm)" at 4389.76,4889.76 h50
  text "PTH" at 5309.5,4889.76 h50
  text "Round" at 5736.39,4889.76 h50
  text "L1-Top - L4-Bottom" at 6353.23,4889.76 h50
  text "Pad" at 7349.94,4889.76 h50
  text "Rounded" at 7846.81,4889.76 h50
  text "Drilled" at 8473.65,4889.76 h50
  text "8" at 3886.56,4764.76 h50
  text "98.43mil (2.500mm)" at 4389.76,4764.76 h50
  text "PTH" at 5309.5,4764.76 h50
  text "Round" at 5736.39,4764.76 h50
  text "L1-Top - L4-Bottom" at 6353.23,4764.76 h50
  text "Pad" at 7349.94,4764.76 h50
  text "Rounded" at 7846.81,4764.76 h50
  text "Drilled" at 8473.65,4764.76 h50
  text "9" at 3886.56,4639.76 h50
  text "44.88mil (1.140mm)" at 4389.76,4639.76 h50
  text "PTH" at 5309.5,4639.76 h50
  text "Round" at 5736.39,4639.76 h50
  text "L1-Top - L4-Bottom" at 6353.23,4639.76 h50
  text "Pad" at 7349.94,4639.76 h50
  text "*" at 7846.81,4639.76 h50
  text "Drilled" at 8473.65,4639.76 h50
  text "40" at 3886.56,4514.76 h50
  text "15.00mil (0.381mm)" at 4389.76,4514.76 h50
  text "PTH" at 5309.5,4514.76 h50
  text "Round" at 5736.39,4514.76 h50
  text "L1-Top - L4-Bottom" at 6353.23,4514.76 h50
  text "Via" at 7349.94,4514.76 h50
  text "Rounded" at 7846.81,4514.76 h50
  text "Drilled" at 8473.65,4514.76 h50
  text "74" at 3886.56,4389.76 h50
  text "11.81mil (0.300mm)" at 4389.76,4389.76 h50
  text "PTH" at 5309.5,4389.76 h50
  text "Round" at 5736.39,4389.76 h50
  text "L1-Top - L4-Bottom" at 6353.23,4389.76 h50
  text "Via" at 7349.94,4389.76 h50
  text "Rounded" at 7846.81,4389.76 h50
  text "Drilled" at 8473.65,4389.76 h50
  text "160" at 3886.56,4264.76 h50
  text "31.50mil (0.800mm)" at 4389.76,4264.76 h50
  text "PTH" at 5309.5,4264.76 h50
  text "Round" at 5736.39,4264.76 h50
  text "L1-Top - L4-Bottom" at 6353.23,4264.76 h50
  text "Pad" at 7349.94,4264.76 h50
  text "*" at 7846.81,4264.76 h50
  text "Drilled" at 8473.65,4264.76 h50
  text "192" at 3886.56,4139.76 h50
  text "8.00mil (0.203mm)" at 4389.76,4139.76 h50
  text "PTH" at 5309.5,4139.76 h50
  text "Round" at 5736.39,4139.76 h50
  text "L1-Top - L4-Bottom" at 6353.23,4139.76 h50
  text "Via" at 7349.94,4139.76 h50
  text "Rounded" at 7846.81,4139.76 h50
  text "Drilled" at 8473.65,4139.76 h50
  text "508 Total" at 3886.56,4014.76 h50
  text "Layer" at 3609.59,-3700.37 h60
  text "Name" at 4019.5,-3700.37 h60
  text "Material" at 4949.24,-3700.37 h60
  text "Thickness" at 5809.01,-3700.37 h60
  text "Constant" at 6458.85,-3700.37 h60
  text "Board Layer Stack" at 7028.71,-3700.37 h60
  text "1" at 3609.59,-3820.37 h60
  text "Top Overlay" at 4019.5,-3820.37 h60
  text "2" at 3609.59,-3940.37 h60
  text "Top Solder" at 4019.5,-3940.37 h60
  text "Solder Resist" at 4949.24,-3940.37 h60
  text "0.40mil" at 5809.01,-3940.37 h60
  text "3.5" at 6458.85,-3940.37 h60
  text "3" at 3609.59,-4060.37 h60
  text "L1-Top" at 4019.5,-4060.37 h60
  text "Copper" at 4949.24,-4060.37 h60
  text "2.10mil" at 5809.01,-4060.37 h60
  text "4" at 3609.59,-4180.37 h60
  text "Dielectric1" at 4019.5,-4180.37 h60
  text "370HR" at 4949.24,-4180.37 h60
  text "7.30mil" at 5809.01,-4180.37 h60
  text "4.2" at 6458.85,-4180.37 h60
  text "5" at 3609.59,-4300.37 h60
  text "L2-Plane-1" at 4019.5,-4300.37 h60
  text "Copper" at 4949.24,-4300.37 h60
  text "1.40mil" at 5809.01,-4300.37 h60
  text "6" at 3609.59,-4420.37 h60
  text "Dielectric 3" at 4019.5,-4420.37 h60
  text "370HR" at 4949.24,-4420.37 h60
  text "39.00mil" at 5809.01,-4420.37 h60
  text "4.2" at 6458.85,-4420.37 h60
  text "7" at 3609.59,-4540.37 h60
  text "L3-Plane-2" at 4019.5,-4540.37 h60
  text "Copper" at 4949.24,-4540.37 h60
  text "1.40mil" at 5809.01,-4540.37 h60
  text "8" at 3609.59,-4660.37 h60
  text "Dielectric 2" at 4019.5,-4660.37 h60
  text "370HR" at 4949.24,-4660.37 h60
  text "7.30mil" at 5809.01,-4660.37 h60
  text "4.2" at 6458.85,-4660.37 h60
  text "9" at 3609.59,-4780.37 h60
  text "L4-Bottom" at 4019.5,-4780.37 h60
  text "Copper" at 4949.24,-4780.37 h60
  text "2.10mil" at 5809.01,-4780.37 h60
  text "10" at 3609.59,-4900.37 h60
  text "Bottom Solder" at 4019.5,-4900.37 h60
  text "Solder Resist" at 4949.24,-4900.37 h60
  text "0.40mil" at 5809.01,-4900.37 h60
  text "3.5" at 6458.85,-4900.37 h60
  text "11" at 3609.59,-5020.37 h60
  text "Bottom Overlay" at 4019.5,-5020.37 h60
Doc-Assy-Top:
  lines w2.64: -452.76,229.19 -347.14,229.19 ; -452.76,1351.4 -347.14,1351.4 ; -452.76,2473.61 -347.14,2473.61 ; 893.9,-787.4 893.9,-681.78 ; 893.9,3384.58 893.9,3490.2 ; 2346.17,-787.4 2346.17,-681.78 ; 2346.17,3384.58 2346.17,3490.2 ; 2768.65,-787.4 5145.09,-787.4 ; 3456.84,-681.78 3456.84,-366.59 ; 3456.84,-556.2 5039.48,-556.2 ; 3798.44,-787.4 3798.44,-681.78 ; 3798.44,3384.58 3798.44,3490.2 ; 4140.31,-428.96 4140.31,-179.62 ; 4547.81,-556.2 4547.81,-429.12 ; 5039.48,-429.12 3456.84,-429.12 3456.84,-179.62 5039.48,-179.62 ; 5039.48,229.19 5145.09,229.19 ; 5039.48,1351.4 5145.09,1351.4 ; 5039.48,2473.61 5145.09,2473.61 ; 5145.09,-787.4 5145.09,3490.2 -452.76,3490.2 -452.76,-787.4 5145.09,-787.4 ; -347.14,-681.78 -347.14,3384.58 5039.48,3384.58 5039.48,-681.78 -347.14,-681.78
  text "1" at 155.26,3420.57 h36.97
  text "2" at 1607.89,3420.57 h36.97
  text "3" at 3057.52,3420.57 h36.97
  text "4" at 4510.33,3420.57 h36.97
  text "A" at -414.81,2986.92 h36.97
  text "A" at 5080.75,2986.92 h36.97
  text "B" at -414.81,1864.71 h36.97
  text "B" at 5080.75,1864.71 h36.97
  text "C" at -414.81,742.5 h36.97
  text "C" at 5080.75,742.5 h36.97
  text "TITLE:" at 3497.85,-221.2 h23.76
  text "Opal Kelly" at 4181.89,-237.84 h36.97
  text "13500 SW 72nd Ave Suite 100" at 4181.89,-300.21 h36.97
  text "Portland, OR 97223" at 4181.89,-352.19 h36.97
  text "BRK5305 / Assembly Drawing" at 3514.95,-353.08 h36.97
  text "D" at -414.81,-377.07 h36.97
  text "D" at 5080.75,-377.07 h36.97
  text "www.opalkelly.com" at 4181.89,-404.17 h36.97
  text "(Top)" at 3514.95,-413.28 h36.97
  text "DATE:" at 3497.85,-470.7 h23.76
  text "TIME:" at 3928.18,-471.37 h23.76
  text "SIZE:" at 4597.71,-471.37 h23.76
  text ".PRINT_DATE" at 3517.97,-534.75 h36.97
  text ".Print_Time" at 3954.58,-534.75 h36.97
  text "ANSI A" at 4622.66,-534.75 h36.97
  text "FILE NAME:" at 3497.85,-595.45 h23.76
  text ".PCB_FILE_NAME" at 3518.65,-657.82 h36.97
  text "1" at 155.26,-754.74 h36.97
  text "2" at 1607.89,-754.74 h36.97
  text "3" at 3057.52,-754.74 h36.97
  text "4" at 4510.33,-754.74 h36.97
Doc-Assy-Bot:
  lines w2.64: -452.56,229.98 -346.88,229.98 ; -452.56,1352.84 -346.88,1352.84 ; -452.56,2475.71 -346.88,2475.71 ; -346.88,-555.87 1236.68,-555.87 ; -346.88,-428.71 1236.68,-428.71 1236.68,-179.07 -346.88,-179.07 ; 145.07,-555.87 145.07,-428.71 ; 552.82,-428.55 552.82,-179.07 ; 894.88,-787.2 894.88,-681.52 ; 894.88,3387.21 894.88,3492.89 ; 1236.68,-681.52 1236.68,-366.14 ; 1925.27,-787.2 -452.56,-787.2 ; 2348,-787.2 2348,-681.52 ; 2348,3387.21 2348,3492.89 ; 3801.11,-787.2 3801.11,-681.52 ; 3801.11,3387.21 3801.11,3492.89 ; 5042.87,229.98 5148.55,229.98 ; 5042.87,1352.84 5148.55,1352.84 ; 5042.87,2475.71 5148.55,2475.71 ; -452.56,-787.2 -452.56,3492.89 5148.55,3492.89 5148.55,-787.2 -452.56,-787.2 ; -346.88,-681.52 -346.88,3387.21 5042.87,3387.21 5042.87,-681.52 -346.88,-681.52
  text "4" at 182.58,3423.22 h36.99
  text "3" at 1636.23,3423.22 h36.99
  text "2" at 3086.71,3423.22 h36.99
  text "1" at 4540.18,3423.22 h36.99
  text "A" at -388.17,2989.32 h36.99
  text "A" at 5110.58,2989.32 h36.99
  text "B" at -388.17,1866.45 h36.99
  text "B" at 5110.58,1866.45 h36.99
  text "C" at -388.17,743.59 h36.99
  text "C" at 5110.58,743.59 h36.99
  text "TITLE:" at 1195.64,-220.68 h23.78
  text "Opal Kelly" at 511.21,-237.32 h36.99
  text "13500 SW 72nd Ave Suite 100" at 511.21,-299.73 h36.99
  text "Portland, OR 97223" at 511.21,-351.74 h36.99
  text "BRK5305 / Assembly Drawing" at 1178.54,-352.63 h36.99
  text "D" at -388.17,-376.63 h36.99
  text "D" at 5110.58,-376.63 h36.99
  text "www.opalkelly.com" at 511.21,-403.75 h36.99
  text "(Bottom)" at 1178.54,-412.87 h36.99
  text "DATE:" at 1195.64,-470.32 h23.78
  text "SIZE:" at 95.14,-470.99 h23.78
  text "TIME:" at 765.06,-470.99 h23.78
  text "ANSI A" at 70.18,-534.4 h36.99
  text ".Print_Time" at 738.64,-534.4 h36.99
  text ".PRINT_DATE" at 1175.52,-534.4 h36.99
  text "FILE NAME:" at 1195.64,-595.14 h23.78
  text ".PCB_FILE_NAME" at 1174.84,-657.55 h36.99
  text "4" at 182.58,-754.52 h36.99
  text "3" at 1636.23,-754.52 h36.99
  text "2" at 3086.71,-754.52 h36.99
  text "1" at 4540.18,-754.52 h36.99
Doc-Fab:
  lines w5: -852,449 -652,449 ; -852,2574 -652,2574 ; -852,4699 -652,4699 ; 1698,-1476 1698,-1276 ; 1698,6424 1698,6624 ; 4448,-1476 4448,-1276 ; 4448,6424 4448,6624 ; 5248,-1476 9748,-1476 ; 6551.15,-1276 6551.15,-679.15 ; 6551.15,-1038.2 9548,-1038.2 ; 7198,-1476 7198,-1276 ; 7198,6424 7198,6624 ; 7845.35,-797.26 7845.35,-325.12 ; 8617,-1038.2 8617,-797.56 ; 9548,-797.56 6551.15,-797.56 6551.15,-325.12 9548,-325.12 ; 9548,449 9748,449 ; 9548,2574 9748,2574 ; 9548,4699 9748,4699 ; 9748,-1476 9748,6624 -852,6624 -852,-1476 9748,-1476 ; -652,-1276 -652,6424 9548,6424 9548,-1276 -652,-1276
  text "1" at 299.34,6492.15 h70
  text "2" at 3050,6492.15 h70
  text "3" at 5795,6492.15 h70
  text "4" at 8546.01,6492.15 h70
  text "A" at -780.15,5671 h70
  text "A" at 9626.15,5671 h70
  text "B" at -780.15,3546 h70
  text "B" at 9626.15,3546 h70
  text "C" at -780.15,1421 h70
  text "C" at 9626.15,1421 h70
  text "TITLE:" at 6628.81,-403.86 h45
  text "Opal Kelly" at 7924.09,-435.35 h70
  text "13500 SW 72nd Ave Suite 100" at 7924.09,-553.46 h70
  text "Portland, OR 97223" at 7924.09,-651.89 h70
  text "BRK5305 / Fabrication Drawing" at 6659.9,-679.45 h70
  text "D" at -780.15,-699 h70
  text "D" at 9626.15,-699 h70
  text "www.opalkelly.com" at 7924.09,-750.32 h70
  text "DATE:" at 6628.81,-876.3 h45
  text "TIME:" at 7443.67,-877.57 h45
  text "SIZE:" at 8711.49,-877.57 h45
  text ".PRINT_DATE" at 6666.9,-997.57 h70
  text ".Print_Time" at 7493.67,-997.57 h70
  text "ANSI A" at 8758.73,-997.57 h70
  text "FILE NAME:" at 6628.81,-1112.52 h45
  text ".PCB_FILE_NAME" at 6668.18,-1230.63 h70
  text "1" at 299.34,-1414.15 h70
  text "2" at 3050,-1414.15 h70
  text "3" at 5795,-1414.15 h70
  text "4" at 8546.01,-1414.15 h70

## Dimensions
0,0 to 0,3149.61 on Dimensions
0,0 to 4724.41,0 on Dimensions
0,0 to 118.11,118.11 on MTG Locations
0,0 to 4606.3,118.11 on MTG Locations
0,0 to 118.11,118.11 on MTG Locations
0,0 to 118.11,3031.5 on MTG Locations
